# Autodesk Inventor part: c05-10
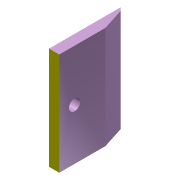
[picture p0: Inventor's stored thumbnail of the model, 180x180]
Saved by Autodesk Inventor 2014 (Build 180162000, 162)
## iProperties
Created: 2010-11
Part Number: c05-10
Material: Generic
Document SubType Name: Modeling
Designer: Thom Tremblay
Density: 1 g/cm^3
Appearance: Satin - Lavender
Author: Thom Tremblay
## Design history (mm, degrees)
sketch "Sketch1"
  geometry: L1 (0, 0)-(10, 0); L2 (10, 0)-(10, 70); L3 (10, 70)-(0, 70); L4 (0, 70)-(0, 0); L5 (3, 67)-(10, 45); L6 (0, 70)-(3, 67); 1 further point
  constraints: 12 end point, 2 parallel, 2 point on line, 1 horizontal, 1 perpendicular
  dimensions: "d0" = 10 distance of L3.end L2.end; "d1" = 70 distance of L2.end L1.end; "d3" = 25 vertical distance of point (2.045, 70) L5.end; "d6" = 45 deg angle of L4 L6; "d7" = 3 distance from line of L4 L5.start
extrude "Extrusion1" new body sketch "Sketch1" stored distance "d4" = 100; taper "d5" = 0 deg
hole "Hole1" diameter "d10" = 11; stored, may be unused: countersink angle "d14" = 90 deg, drill point angle "d16" = 118 deg; dims "d8" = 50, "d9" = 15, "d11" = 6, "d12" = 4, "d13" = 2, "d15" = 8
body "Solid1"
